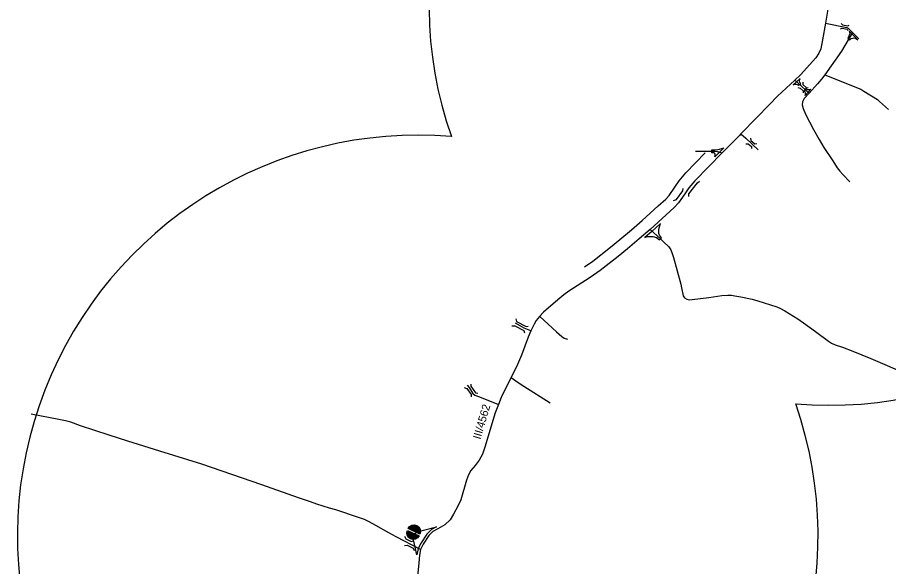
# Model space of a CAD drawing. Extents: x -546703 to -534152, y -1046534 to -1035676.
# Drawn here: x -544655 to -543567, y -1042315 to -1041629 of the extents above; entities that cross this region are included whole.
import ezdxf

# ---------------------------------------------------------------- set-up
doc = ezdxf.new("R2010")
doc.units = 0
for name, color, linetype in [('Vrstva 11', 7, 'Continuous'), ('Vrstva 14', 7, 'Continuous'), ('Vrstva 17', 7, 'Continuous'), ('Vrstva 23', 7, 'Continuous'), ('Vrstva 26', 7, 'Continuous'), ('Vrstva 4', 7, 'Continuous'), ('Vrstva 7', 7, 'Continuous'), ('Vrstva 8', 7, 'Continuous')]:
    doc.layers.add(name, color=color, linetype=linetype)

msp = doc.modelspace()

# ---------------------------------------------------------------- linework, layer by layer
at = {"layer": 'Vrstva 11'}
for points in [[(-543808.1, -1041796.4), (-543787.5, -1041796.4), (-543784.3, -1041796.5), (-543780.8, -1041796.8), (-543774.5, -1041798.4)], [(-544257.1, -1042244.2), (-544265.2, -1042242.1), (-544280.8, -1042237.2), (-544289, -1042234.3), (-544303.7, -1042229.2), (-544349.6, -1042212.8), (-544424.5, -1042187.2), (-544477.1, -1042171.1), (-544517, -1042158.5), (-544540.3, -1042151.1), (-544576.2, -1042139.1), (-544588.3, -1042134.9), (-544594.9, -1042133.2), (-544603.1, -1042131.3), (-544637.6, -1042124.7)]]:
    msp.add_lwpolyline(points, dxfattribs=at)
msp.add_lwpolyline([(-543787.5, -1041794.7), (-543782, -1041794.5), (-543777.8, -1041793.9), (-543775.2, -1041793.2), (-543772.4, -1041792), (-543776.7, -1041796.3), (-543783.8, -1041803.5), (-543783.4, -1041801.7), (-543783.4, -1041800.3), (-543783.9, -1041799.3), (-543784.8, -1041798.5), (-543787.5, -1041798.2)], close=True, dxfattribs=at)
at = {"layer": 'Vrstva 14'}
msp.add_lwpolyline([(-543645.6, -1041636.5), (-543619.1, -1041641.7), (-543617.3, -1041642.6), (-543616.5, -1041643.5)], dxfattribs=at)
at = {"layer": 'Vrstva 17'}
msp.add_lwpolyline([(-543946.8, -1041940.9), (-543936.1, -1041933.5), (-543914, -1041916.2), (-543902.4, -1041906.7), (-543887.9, -1041894.5), (-543874.5, -1041883.1), (-543854.6, -1041864.6), (-543845.1, -1041856.1), (-543840.9, -1041851.6), (-543833.7, -1041841.3), (-543828.5, -1041833.3), (-543820.1, -1041823.2), (-543795.7, -1041798.5)], dxfattribs=at)
at = {"layer": 'Vrstva 23'}
for points in [[(-544164.1, -1042280.6), (-544166.6, -1042278.7), (-544168.3, -1042276), (-544168.7, -1042272.8), (-544167.9, -1042269.8), (-544153.3, -1042276.8), (-544155.2, -1042279.3), (-544157.9, -1042280.9), (-544161.1, -1042281.4)], [(-544156.1, -1042263.7), (-544153.6, -1042265.6), (-544151.9, -1042268.3), (-544151.5, -1042271.5), (-544152.3, -1042274.5), (-544166.9, -1042267.5), (-544165, -1042265), (-544162.3, -1042263.4), (-544159.1, -1042262.9)], [(-544156.4, -1042264.3), (-544154, -1042266), (-544152.5, -1042268.5), (-544152.1, -1042271.4), (-544152.7, -1042273.7), (-544166, -1042267.3), (-544164.6, -1042265.5), (-544162.1, -1042264), (-544159.2, -1042263.6)], [(-544156.6, -1042264.8), (-544154.5, -1042266.4), (-544153.1, -1042268.7), (-544152.7, -1042271.4), (-544153.1, -1042272.8), (-544165.1, -1042267.1), (-544164.2, -1042265.9), (-544161.9, -1042264.5), (-544159.2, -1042264.2)], [(-544156.9, -1042265.4), (-544154.9, -1042266.8), (-544153.7, -1042269), (-544153.3, -1042271.4), (-544153.5, -1042272), (-544164.1, -1042266.9), (-544163.8, -1042266.4), (-544161.7, -1042265.1), (-544159.2, -1042264.8)], [(-544157.1, -1042265.9), (-544155.4, -1042267.3), (-544154.3, -1042269.2), (-544154, -1042271.1), (-544163.1, -1042266.7), (-544161.5, -1042265.7), (-544159.3, -1042265.4)], [(-544157.4, -1042266.5), (-544155.8, -1042267.7), (-544154.8, -1042269.4), (-544154.7, -1042270), (-544161.8, -1042266.6), (-544161.3, -1042266.3), (-544159.3, -1042266)], [(-544157.7, -1042267), (-544156.3, -1042268.1), (-544155.8, -1042268.8), (-544160.2, -1042266.7), (-544159.3, -1042266.6)], [(-544163.8, -1042280), (-544166.2, -1042278.3), (-544167.7, -1042275.8), (-544168.1, -1042272.9), (-544167.5, -1042270.6), (-544154.2, -1042277), (-544155.6, -1042278.8), (-544158.1, -1042280.3), (-544161, -1042280.8)], [(-544163.6, -1042279.5), (-544165.7, -1042277.9), (-544167.1, -1042275.6), (-544167.5, -1042272.9), (-544167.1, -1042271.5), (-544155.1, -1042277.2), (-544156, -1042278.4), (-544158.3, -1042279.8), (-544161, -1042280.1)], [(-544163.3, -1042278.9), (-544165.3, -1042277.5), (-544166.5, -1042275.4), (-544166.9, -1042272.9), (-544166.7, -1042272.3), (-544156.1, -1042277.4), (-544156.4, -1042277.9), (-544158.5, -1042279.2), (-544161, -1042279.5)], [(-544163.1, -1042278.4), (-544164.8, -1042277.1), (-544165.9, -1042275.2), (-544166.2, -1042273.3), (-544157.1, -1042277.6), (-544158.7, -1042278.6), (-544160.9, -1042278.9)], [(-544162.8, -1042277.8), (-544164.4, -1042276.6), (-544165.4, -1042275), (-544165.5, -1042274.3), (-544158.4, -1042277.7), (-544158.9, -1042278), (-544160.9, -1042278.3)], [(-544162.5, -1042277.3), (-544163.9, -1042276.2), (-544164.4, -1042275.5), (-544160, -1042277.6), (-544160.9, -1042277.7)]]:
    msp.add_lwpolyline(points, close=True, dxfattribs=at)
at = {"layer": 'Vrstva 26'}
for centre, start, end in [((-543640.8, -1041613.6), 265.1835, 199.2198), ((-544154.9, -1042276.4), 85.1835, 19.2198)]:
    msp.add_arc(centre, 500, start, end, dxfattribs=at)
at = {"layer": 'Vrstva 4'}
msp.add_lwpolyline([(-543642.5, -1041619.1), (-543645.6, -1041636.5), (-543649.5, -1041657.4), (-543651.6, -1041668.4), (-543654, -1041674.1), (-543657.7, -1041679.6), (-543676.8, -1041701.1), (-543683.8, -1041707.5), (-543705.4, -1041727.7), (-543715.6, -1041738.1), (-543731.9, -1041754.6), (-543751.3, -1041774.8), (-543753.1, -1041776.7), (-543774.5, -1041798.4), (-543808.9, -1041833.3), (-543816.4, -1041842.3), (-543821.3, -1041849.7), (-543829.2, -1041861), (-543834.6, -1041866.8), (-543844.5, -1041875.7), (-543864.5, -1041894.3), (-543878.2, -1041905.9), (-543892.8, -1041918.3), (-543904.6, -1041927.9), (-543927.1, -1041945.5), (-543939.5, -1041954.1), (-543966.1, -1041971), (-543972.5, -1041975.6), (-543980.1, -1041982), (-543997.8, -1041997.3), (-544002.9, -1042002.7), (-544006.9, -1042007.9), (-544009.5, -1042012.4), (-544013.7, -1042020.7), (-544016.9, -1042028.4), (-544025.2, -1042051.2), (-544030.3, -1042062.9), (-544050.5, -1042103.9), (-544054.2, -1042112.7), (-544058.3, -1042123.2), (-544070.9, -1042166), (-544074, -1042174.8), (-544078, -1042182.2), (-544083.2, -1042188.8), (-544088.4, -1042195.2), (-544091.5, -1042200.5), (-544093.8, -1042207.2), (-544101.2, -1042231.6), (-544105, -1042239.8), (-544110.1, -1042249.8), (-544114.6, -1042256.7), (-544120.9, -1042262.8), (-544129.9, -1042268.1), (-544136.1, -1042271.3), (-544141.1, -1042276.3), (-544148.1, -1042286.9), (-544151.5, -1042293.6), (-544152.9, -1042300.6), (-544153.7, -1042310.3), (-544157.6, -1042353)], dxfattribs=at)
at = {"layer": 'Vrstva 7'}
msp.add_line((-543683.8, -1041707.5), (-543666.1, -1041723.9), dxfattribs=at)
for points in [[(-543611.7, -1041648.2), (-543625.6, -1041671.5), (-543646.3, -1041701.2), (-543650.6, -1041706.5), (-543655.7, -1041712.4), (-543666.1, -1041723.9), (-543672.3, -1041730.6), (-543674.3, -1041734.6), (-543674.7, -1041738.6), (-543673.6, -1041743.2), (-543670.6, -1041750.2), (-543660.4, -1041769.1), (-543653.5, -1041781.9), (-543647.5, -1041791.9), (-543636.6, -1041808.4), (-543631.1, -1041817.1), (-543627.8, -1041821.2), (-543623.9, -1041825.6), (-543615.4, -1041834.7)], [(-543616.5, -1041643.5), (-543614.8, -1041645.2), (-543611.7, -1041648.2), (-543604, -1041656.1)], [(-543646.3, -1041701.1), (-543601.4, -1041718.9), (-543597.6, -1041721.3), (-543580.6, -1041732), (-543578, -1041734.2), (-543567.1, -1041744.3)], [(-543751.3, -1041774.8), (-543745.3, -1041780.3), (-543729.6, -1041794.5)], [(-543864.5, -1041894.3), (-543851.8, -1041905.7), (-543847.9, -1041909.4), (-543841.2, -1041915.9), (-543838.8, -1041919.5), (-543837, -1041924.2), (-543835.4, -1041928.9), (-543826.3, -1041962.4), (-543825.3, -1041967), (-543823.2, -1041977.1), (-543821.6, -1041979.6), (-543818.9, -1041981.3), (-543815.5, -1041981.8), (-543812, -1041981.5), (-543791.4, -1041978.9), (-543774.9, -1041976.7), (-543767.5, -1041976.1), (-543762.9, -1041976.2), (-543758.7, -1041976.9), (-543751.4, -1041978.4), (-543737.1, -1041981), (-543730.2, -1041983.1), (-543706.5, -1041990.7), (-543701.7, -1041992.8), (-543696.3, -1041995.8), (-543680.1, -1042005.8), (-543673.1, -1042010.5), (-543658, -1042021.7), (-543642, -1042033.6), (-543638, -1042035.9), (-543633.4, -1042038), (-543624.2, -1042041.1), (-543611.4, -1042046), (-543589.1, -1042055.4), (-543541.5, -1042075.7)], [(-544002.4, -1042002.6), (-543981.7, -1042021.9), (-543975, -1042027.8), (-543972.2, -1042029.8), (-543967.9, -1042031.2)], [(-544013.7, -1042020.7), (-544021.8, -1042017.2), (-544033, -1042011.2)], [(-543989.4, -1042111), (-544022.4, -1042090), (-544029.3, -1042085.6), (-544038.4, -1042079.4)], [(-544093.2, -1042088.4), (-544090.7, -1042091.4), (-544085.9, -1042098.8), (-544083.5, -1042100.8), (-544077.6, -1042103.1), (-544054.2, -1042112.7)], [(-544151.5, -1042293.6), (-544181.9, -1042277.8), (-544190.8, -1042272.7), (-544207.1, -1042263.6), (-544215.7, -1042259.1), (-544221.6, -1042256.3), (-544230.1, -1042253.4), (-544256, -1042244.5), (-544257.1, -1042244.2)]]:
    msp.add_lwpolyline(points, dxfattribs=at)
for points in [[(-543616, -1041646.4), (-543615.5, -1041648), (-543615.4, -1041648.8), (-543615.6, -1041650.5), (-543616.5, -1041652.6), (-543617.9, -1041655.2), (-543615, -1041657.2), (-543613.6, -1041655.7), (-543612, -1041655.1), (-543610.1, -1041654.9), (-543608.1, -1041655.2), (-543605.3, -1041657.3), (-543613, -1041649.4)], [(-543681.8, -1041709.7), (-543685.9, -1041713.5), (-543684.2, -1041712.8), (-543682.3, -1041712.7), (-543680.8, -1041713.1), (-543679.3, -1041714.1), (-543676.6, -1041711.8), (-543677.6, -1041710.5), (-543678.1, -1041709), (-543678.2, -1041707.5), (-543677.3, -1041705.6)], [(-543664, -1041719), (-543667.4, -1041722.7), (-543671.1, -1041726.7), (-543670.6, -1041725.2), (-543670.5, -1041723.8), (-543670.9, -1041722.4), (-543672, -1041720.9), (-543669.7, -1041718.2), (-543668.3, -1041719.2), (-543666.9, -1041719.5), (-543665.4, -1041719.4)], [(-543850.6, -1041904.5), (-543852.8, -1041901.4), (-543853.6, -1041899.1), (-543853.9, -1041897.2), (-543853.9, -1041894.9), (-543853.5, -1041891.9), (-543851.8, -1041886.6), (-543862.5, -1041896.6), (-543871.3, -1041904), (-543868.4, -1041902.9), (-543864.8, -1041902.7), (-543861.2, -1041902.9), (-543856.8, -1041904.3), (-543853, -1041907)], [(-544155.9, -1042300.2), (-544160.2, -1042281.6), (-544160.2, -1042278.8), (-544159.7, -1042276.1), (-544158.4, -1042273.7), (-544156.3, -1042272.1), (-544153.2, -1042270.8), (-544149.5, -1042270), (-544131.3, -1042265.5), (-544137.9, -1042268.9), (-544143.4, -1042274.4), (-544150.7, -1042285.4), (-544154.3, -1042292.6)]]:
    msp.add_lwpolyline(points, close=True, dxfattribs=at)
at = {"layer": 'Vrstva 8'}
for points in [[(-543626.1, -1041636.9), (-543624.5, -1041638.7), (-543617.9, -1041639.9), (-543615.9, -1041638.8)], [(-543626.8, -1041643.7), (-543624.7, -1041642.8), (-543618.6, -1041644), (-543617.5, -1041645.8)], [(-543674.1, -1041710.3), (-543673.9, -1041713.2), (-543669.5, -1041717.2), (-543667.1, -1041716.8)], [(-543680, -1041716.8), (-543677.3, -1041717.5), (-543673.5, -1041721), (-543673.4, -1041723.5)], [(-543739.1, -1041780.2), (-543738.7, -1041782.8), (-543733.8, -1041787), (-543731.2, -1041786.8)], [(-543744.9, -1041787.1), (-543742, -1041787.1), (-543738, -1041790.7), (-543737.9, -1041793.2)], [(-543816.1, -1041852.8), (-543816.3, -1041849.7), (-543805.6, -1041835.8), (-543802.8, -1041833.7)], [(-543835.6, -1041857.9), (-543831.6, -1041856.8), (-543823.6, -1041845.8), (-543823.5, -1041843.1)], [(-544032.4, -1042005.7), (-544031.4, -1042008.9), (-544019.6, -1042015.2), (-544016.8, -1042014.7)], [(-544037.4, -1042014.4), (-544033.8, -1042014.3), (-544022.4, -1042020.3), (-544021.6, -1042023)], [(-544097, -1042091.4), (-544093.7, -1042092.5), (-544088, -1042100.3), (-544088.2, -1042102.9)], [(-544088.4, -1042087.4), (-544088.6, -1042089.9), (-544082.9, -1042098), (-544080, -1042098.7)], [(-544171.3, -1042277.2), (-544169.9, -1042280.4), (-544163.1, -1042283.6), (-544160.1, -1042283)], [(-544171.6, -1042288.7), (-544168, -1042288.2), (-544160.7, -1042292), (-544159.5, -1042294.9)]]:
    msp.add_lwpolyline(points, dxfattribs=at)

# ---------------------------------------------------------------- texts
at = {"layer": 'Vrstva 4'}
msp.add_text('III/4562', height=10, rotation=73.6111, dxfattribs=at).set_placement((-544076.6, -1042156.9))

doc.saveas('drawing.dxf')
